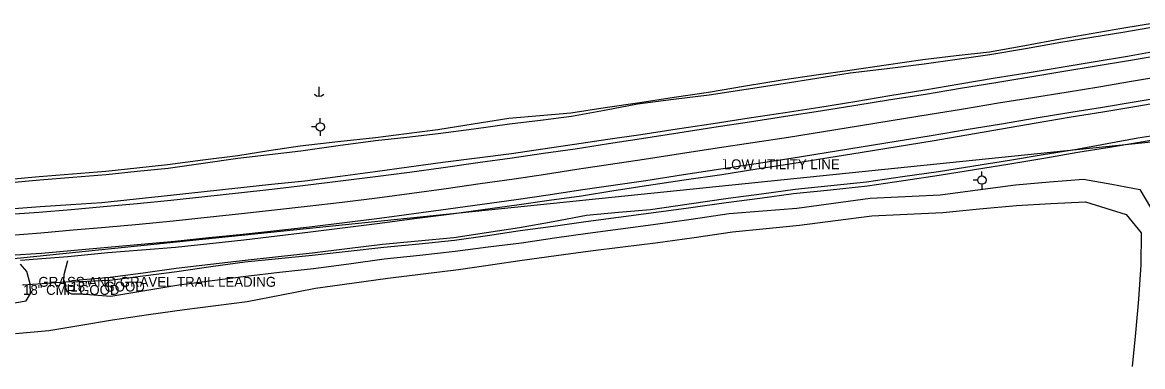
# Model space of a CAD drawing. Extents: x 1734049 to 1769984, y 344166 to 379510.
# Drawn here: x 1735411 to 1735978, y 378133 to 378307 of the extents above; entities that cross this region are included whole.
import ezdxf

# ---------------------------------------------------------------- set-up
doc = ezdxf.new("R2010")
doc.units = 0
for name, color, linetype in [('S_BASELINE', 7, 'Continuous'), ('S_DITCHLINE', 7, 'Continuous'), ('S_DRG_PT_SYM', 7, 'Continuous'), ('S_EDGE_PAVEMENT', 7, 'Continuous'), ('S_ELECTRIC_UTILITIES_ANNOT', 7, 'Continuous'), ('S_MSC_PT_SYM', 7, 'Continuous'), ('S_PAVEMENT_CROWN', 7, 'Continuous'), ('S_SHOULDER', 7, 'Continuous'), ('S_SIDE_DRAIN', 7, 'Continuous'), ('S_SIDE_DRAIN_ANNOT', 7, 'Continuous'), ('S_SURVEY_TEXT_ANNOT', 7, 'Continuous'), ('S_TRAILS', 7, 'Continuous'), ('S_UTILITY_POLE', 7, 'Continuous'), ('S_UTL_PT_SYM', 7, 'Continuous')]:
    doc.layers.add(name, color=color, linetype=linetype)

msp = doc.modelspace()

# ---------------------------------------------------------------- linework, layer by layer
at = {"layer": 'S_BASELINE'}
msp.add_line((1735254.82, 378172.19), (1736142.34, 378263.18), dxfattribs=at)
at = {"layer": 'S_DITCHLINE'}
for points in [[(1735402.7, 378227.71), (1735419.25, 378229.23), (1735436.17, 378230.57), (1735453.09, 378231.91), (1735468.69, 378233.61), (1735484.3, 378235.3), (1735502.09, 378237.62), (1735519.89, 378239.93), (1735535.64, 378242.35), (1735551.39, 378244.76), (1735570.5, 378246.9), (1735589.62, 378249.03), (1735605.38, 378251), (1735621.14, 378252.97), (1735639.13, 378255.85), (1735657.12, 378258.72), (1735672.88, 378260.09), (1735688.65, 378261.46), (1735706.08, 378264.08), (1735723.51, 378266.7), (1735740.94, 378269.32), (1735758.36, 378271.95), (1735777.03, 378275.08), (1735795.7, 378278.22), (1735812.83, 378280.67), (1735829.95, 378283.13), (1735848.43, 378285.81), (1735866.92, 378288.49), (1735883.79, 378290.42), (1735900.66, 378292.35), (1735918.65, 378295.6), (1735936.63, 378298.85), (1735952.2, 378301.58), (1735967.77, 378304.3), (1735985.42, 378307.22)], [(1735402.99, 378225.97), (1735419.56, 378227.58), (1735436.35, 378228.93), (1735453.13, 378230.28), (1735468.86, 378231.9), (1735484.6, 378233.52), (1735502.27, 378236), (1735519.93, 378238.48), (1735535.89, 378240.39), (1735551.85, 378242.3), (1735570.79, 378244.91), (1735589.72, 378247.52), (1735605.53, 378249.22), (1735621.34, 378250.92), (1735639.43, 378253.41), (1735657.51, 378255.89), (1735673.21, 378257.79), (1735688.9, 378259.69), (1735705.68, 378262.86), (1735722.46, 378266.04), (1735740.57, 378268.34), (1735758.67, 378270.64), (1735777.46, 378273.5), (1735796.25, 378276.36), (1735813.22, 378279.01), (1735830.19, 378281.65), (1735848.9, 378283.98), (1735867.62, 378286.32), (1735884.29, 378288.66), (1735900.97, 378291), (1735918.94, 378294.1), (1735936.92, 378297.2), (1735952.62, 378299.78), (1735968.33, 378302.37), (1735985.79, 378305.41)], [(1735435.58, 378176.64), (1735455.16, 378178.25), (1735471.94, 378180.5), (1735488.72, 378182.76), (1735506.12, 378184.85), (1735523.53, 378186.94), (1735540.53, 378188.8), (1735557.54, 378190.67), (1735575.34, 378192.78), (1735593.15, 378194.9), (1735611.21, 378196.65), (1735629.28, 378198.41), (1735645.95, 378200.88), (1735662.62, 378203.35), (1735679.59, 378206.47), (1735696.56, 378209.59), (1735712.76, 378211.1), (1735728.95, 378212.61), (1735748.63, 378215.41), (1735768.31, 378218.21), (1735785.25, 378220.49), (1735802.2, 378222.76), (1735820.32, 378224.66), (1735838.44, 378226.56), (1735856.67, 378229.17), (1735874.9, 378231.78), (1735892.86, 378234.65), (1735910.81, 378237.51), (1735927.86, 378240.3), (1735944.91, 378243.09), (1735960.39, 378245.98), (1735975.88, 378248.86), (1735993.41, 378251.45)], [(1735435.6, 378175.95), (1735454.99, 378176.77), (1735471.97, 378178.99), (1735488.95, 378181.22), (1735506.17, 378183.66), (1735523.38, 378186.1), (1735540.5, 378187.73), (1735557.62, 378189.35), (1735575.77, 378191.4), (1735593.92, 378193.45), (1735611.76, 378195.2), (1735629.61, 378196.95), (1735646.31, 378199.4), (1735663.01, 378201.84), (1735679.62, 378204.17), (1735696.23, 378206.49), (1735712.75, 378208.64), (1735729.26, 378210.79), (1735748.26, 378213.43), (1735767.25, 378216.06), (1735784.35, 378218.31), (1735801.46, 378220.56), (1735820.2, 378222.55), (1735838.94, 378224.53), (1735857.1, 378227.18), (1735875.25, 378229.83), (1735893.13, 378232.74), (1735911.02, 378235.66), (1735928.24, 378238.58), (1735945.46, 378241.5), (1735960.59, 378243.99), (1735975.71, 378246.48), (1735993.45, 378249.51)]]:
    msp.add_lwpolyline(points, dxfattribs=at)
at = {"layer": 'S_DRG_PT_SYM'}
for points in [[(1735411.09, 378174.32), (1735411.09, 378174.37), (1735411.09, 378174.32), (1735411.04, 378174.32), (1735411.09, 378174.32), (1735411.09, 378174.27), (1735411.09, 378174.32), (1735411.14, 378174.32)], [(1735435.09, 378176.01), (1735435.09, 378176.06), (1735435.09, 378176.01), (1735435.04, 378176.01), (1735435.09, 378176.01), (1735435.09, 378175.96), (1735435.09, 378176.01), (1735435.14, 378176.01)]]:
    msp.add_lwpolyline(points, dxfattribs=at)
at = {"layer": 'S_EDGE_PAVEMENT'}
for points in [[(1735401.95, 378210.04), (1735419.08, 378211.2), (1735435.43, 378212.59), (1735451.77, 378213.97), (1735468.86, 378215.63), (1735485.96, 378217.3), (1735503.1, 378219.13), (1735520.25, 378220.97), (1735537.19, 378222.88), (1735554.13, 378224.78), (1735571.85, 378226.99), (1735589.58, 378229.2), (1735606.79, 378231.49), (1735624, 378233.79), (1735641.41, 378236.27), (1735658.83, 378238.75), (1735674.81, 378241.01), (1735690.78, 378243.27), (1735707.62, 378245.88), (1735724.46, 378248.48), (1735742.78, 378251.33), (1735761.1, 378254.18), (1735779.21, 378256.97), (1735797.32, 378259.76), (1735815.13, 378262.52), (1735832.94, 378265.28), (1735850.59, 378268.14), (1735868.24, 378270.99), (1735886.11, 378273.92), (1735903.97, 378276.85), (1735921.16, 378279.67), (1735938.34, 378282.5), (1735954.72, 378285.25), (1735971.1, 378287.99), (1735987.96, 378290.84)], [(1735404.36, 378189.37), (1735420.36, 378190.44), (1735437.18, 378191.98), (1735453.99, 378193.51), (1735470.96, 378195.03), (1735487.93, 378196.56), (1735505.27, 378198.33), (1735522.62, 378200.1), (1735539.42, 378201.95), (1735556.22, 378203.8), (1735573.95, 378205.99), (1735591.68, 378208.18), (1735609.05, 378210.49), (1735626.42, 378212.79), (1735643.64, 378215.21), (1735660.85, 378217.63), (1735677.15, 378220.02), (1735693.46, 378222.41), (1735710.01, 378224.85), (1735726.56, 378227.29), (1735745.61, 378230.18), (1735764.67, 378233.08), (1735782.43, 378235.8), (1735800.18, 378238.52), (1735817.98, 378241.36), (1735835.78, 378244.19), (1735853.44, 378247.13), (1735871.09, 378250.06), (1735888.97, 378253.01), (1735906.85, 378255.96), (1735924.4, 378258.86), (1735941.94, 378261.76), (1735957.96, 378264.38), (1735973.99, 378267.01), (1735991.4, 378269.91)]]:
    msp.add_lwpolyline(points, dxfattribs=at)
at = {"layer": 'S_MSC_PT_SYM'}
msp.add_lwpolyline([(1735418.88, 378178.41), (1735418.88, 378178.46), (1735418.88, 378178.41), (1735418.83, 378178.41), (1735418.88, 378178.41), (1735418.88, 378178.36), (1735418.88, 378178.41), (1735418.93, 378178.41)], dxfattribs=at)
at = {"layer": 'S_PAVEMENT_CROWN'}
msp.add_lwpolyline([(1735402.9, 378199.34), (1735420.07, 378200.66), (1735436.43, 378202.15), (1735452.78, 378203.63), (1735469.94, 378205.18), (1735487.1, 378206.73), (1735504.4, 378208.58), (1735521.69, 378210.43), (1735538.4, 378212.28), (1735555.1, 378214.14), (1735572.83, 378216.31), (1735590.56, 378218.48), (1735607.99, 378220.81), (1735625.42, 378223.14), (1735642.63, 378225.61), (1735659.84, 378228.08), (1735675.75, 378230.49), (1735691.65, 378232.91), (1735708.67, 378235.43), (1735725.68, 378237.96), (1735744.19, 378240.83), (1735762.7, 378243.69), (1735780.8, 378246.43), (1735798.89, 378249.16), (1735816.6, 378252.02), (1735834.31, 378254.89), (1735851.96, 378257.73), (1735869.62, 378260.57), (1735887.49, 378263.52), (1735905.36, 378266.46), (1735922.49, 378269.23), (1735939.63, 378271.99), (1735956.17, 378274.7), (1735972.71, 378277.41), (1735989.87, 378280.32)], dxfattribs=at)
at = {"layer": 'S_SHOULDER'}
for points in [[(1735402.16, 378212.73), (1735419.67, 378213.98), (1735435.33, 378215.05), (1735450.99, 378216.12), (1735468.38, 378217.94), (1735485.77, 378219.77), (1735502.86, 378221.63), (1735519.96, 378223.49), (1735536.91, 378225.31), (1735553.87, 378227.12), (1735571.66, 378229.45), (1735589.45, 378231.78), (1735606.58, 378234.11), (1735623.72, 378236.44), (1735641.09, 378238.67), (1735658.46, 378240.89), (1735674.48, 378243.23), (1735690.5, 378245.57), (1735707.31, 378248.06), (1735724.13, 378250.55), (1735742.46, 378253.32), (1735760.79, 378256.1), (1735778.99, 378258.85), (1735797.19, 378261.61), (1735814.83, 378264.38), (1735832.47, 378267.14), (1735850.21, 378270.16), (1735867.95, 378273.18), (1735885.75, 378276.14), (1735903.56, 378279.11), (1735920.79, 378281.94), (1735938.03, 378284.78), (1735954.32, 378287.48), (1735970.6, 378290.17), (1735987.41, 378293.19)], [(1735409.76, 378186.84), (1735420.64, 378187.65), (1735433.78, 378188.69), (1735454.08, 378190.7), (1735471.18, 378192.06), (1735488.28, 378193.42), (1735505.62, 378195.31), (1735522.95, 378197.19), (1735539.86, 378199.17), (1735556.77, 378201.16), (1735574.28, 378203.41), (1735591.79, 378205.66), (1735609.39, 378207.91), (1735626.98, 378210.15), (1735644.1, 378212.53), (1735661.21, 378214.91), (1735677.58, 378217.17), (1735693.94, 378219.44), (1735710.44, 378222.07), (1735726.94, 378224.71), (1735746.04, 378227.51), (1735765.14, 378230.32), (1735782.86, 378233.04), (1735800.57, 378235.76), (1735818.38, 378238.64), (1735836.19, 378241.52), (1735853.94, 378244.41), (1735871.69, 378247.3), (1735889.24, 378250.32), (1735906.78, 378253.35), (1735924.44, 378256.38), (1735942.11, 378259.4), (1735958.21, 378262.02), (1735974.31, 378264.65), (1735991.89, 378267.63)]]:
    msp.add_lwpolyline(points, dxfattribs=at)
at = {"layer": 'S_SIDE_DRAIN'}
msp.add_line((1735411.09, 378174.32), (1735435.09, 378176.01), dxfattribs=at)
at = {"layer": 'S_TRAILS'}
for points in [[(1735433.62, 378186.57), (1735431.71, 378179.48), (1735431.61, 378175.7), (1735433.22, 378171.05), (1735435.68, 378169.81), (1735440.34, 378169.87), (1735455.48, 378168.66), (1735472.76, 378171.49), (1735490.04, 378174.32), (1735506.95, 378176.54), (1735523.87, 378178.76), (1735541.05, 378180.74), (1735558.24, 378182.72), (1735576.15, 378185.1), (1735594.07, 378187.49), (1735612.06, 378189.48), (1735630.05, 378191.48), (1735646.8, 378193.55), (1735663.56, 378195.62), (1735680.4, 378198.11), (1735697.24, 378200.61), (1735713.8, 378202.76), (1735730.36, 378204.92), (1735749.61, 378207.7), (1735768.87, 378210.48), (1735785.95, 378211.84), (1735803.03, 378213.2), (1735821.63, 378215.76), (1735840.23, 378218.32), (1735857.95, 378219.15), (1735875.68, 378219.97), (1735894.79, 378222.51), (1735913.91, 378225.05), (1735931.13, 378226.5), (1735948.35, 378227.95), (1735962.63, 378225.28), (1735976.9, 378222.62), (1735987.21, 378205.25)], [(1735407.18, 378149.82), (1735424.17, 378151.27), (1735440.32, 378154), (1735456.47, 378156.73), (1735474.63, 378159.35), (1735492.79, 378161.97), (1735508.74, 378163.94), (1735524.69, 378165.91), (1735541.98, 378169.32), (1735559.26, 378172.72), (1735577.58, 378175.24), (1735595.9, 378177.75), (1735613.81, 378179.97), (1735631.71, 378182.19), (1735647.85, 378184.49), (1735663.99, 378186.8), (1735681.24, 378189.19), (1735698.5, 378191.59), (1735715, 378193.58), (1735731.5, 378195.57), (1735751.01, 378198.38), (1735770.53, 378201.19), (1735787.52, 378202.89), (1735804.51, 378204.59), (1735822.78, 378206.92), (1735841.06, 378209.24), (1735859.08, 378210.11), (1735877.1, 378210.98), (1735895.72, 378212.79), (1735914.35, 378214.61), (1735931.84, 378215.55), (1735949.33, 378216.49), (1735969.97, 378210.07), (1735977.52, 378200.77), (1735977.38, 378184.55), (1735976.26, 378167.14), (1735974.65, 378150.08), (1735973.04, 378133.01)], [(1735389.88, 378162.43), (1735412.65, 378166.23), (1735414.78, 378169.99), (1735414.72, 378174.85), (1735413.04, 378181.07), (1735409.78, 378184.92)]]:
    msp.add_lwpolyline(points, dxfattribs=at)
at = {"layer": 'S_UTILITY_POLE'}
for p, q in [((1735560.97, 378274.61), (1735560.97, 378269.88)), ((1735561.68, 378256.43), (1735561.68, 378258.68)), ((1735559.59, 378254.3), (1735557.26, 378254.3)), ((1735561.76, 378249.88), (1735561.76, 378252.21)), ((1735896.88, 378229.52), (1735896.88, 378231.76)), ((1735894.79, 378227.38), (1735892.46, 378227.38)), ((1735896.96, 378222.97), (1735896.96, 378225.29))]:
    msp.add_line(p, q, dxfattribs=at)
for centre in [(1735561.68, 378254.32), (1735896.88, 378227.41)]:
    msp.add_circle(centre, 2.13, dxfattribs=at)
msp.add_arc((1735561.03, 378273.31), 3.41, 226.3972, 313.6028, dxfattribs=at)
at = {"layer": 'S_UTL_PT_SYM'}
msp.add_lwpolyline([(1735766.12, 378237.92), (1735766.12, 378237.97), (1735766.12, 378237.92), (1735766.07, 378237.92), (1735766.12, 378237.92), (1735766.12, 378237.87), (1735766.12, 378237.92), (1735766.17, 378237.92)], dxfattribs=at)

# ---------------------------------------------------------------- texts
at = {"layer": 'S_ELECTRIC_UTILITIES_ANNOT'}
msp.add_text('LOW UTILITY LINE', height=5, dxfattribs=at).set_placement((1735766.12, 378232.92))
at = {"layer": 'S_SIDE_DRAIN_ANNOT'}
for s, p in [('18" CMP GOOD', (1735411.09, 378169.32)), ('18"    GOOD ', (1735435.09, 378171.01))]:
    msp.add_text(s, height=5, dxfattribs=at).set_placement(p)
at = {"layer": 'S_SURVEY_TEXT_ANNOT'}
msp.add_text('GRASS AND GRAVEL TRAIL LEADING ', height=5, dxfattribs=at).set_placement((1735418.88, 378173.41))

doc.saveas('drawing.dxf')
